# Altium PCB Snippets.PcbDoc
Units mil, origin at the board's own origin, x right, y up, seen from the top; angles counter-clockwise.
Board outline 6000 x 4000 mil, 2 copper layers (Top Layer, Bottom Layer); 15 components, 12 nets, 30 pads, 5 vias.
Unrouted connection lines stored in the file: 7.
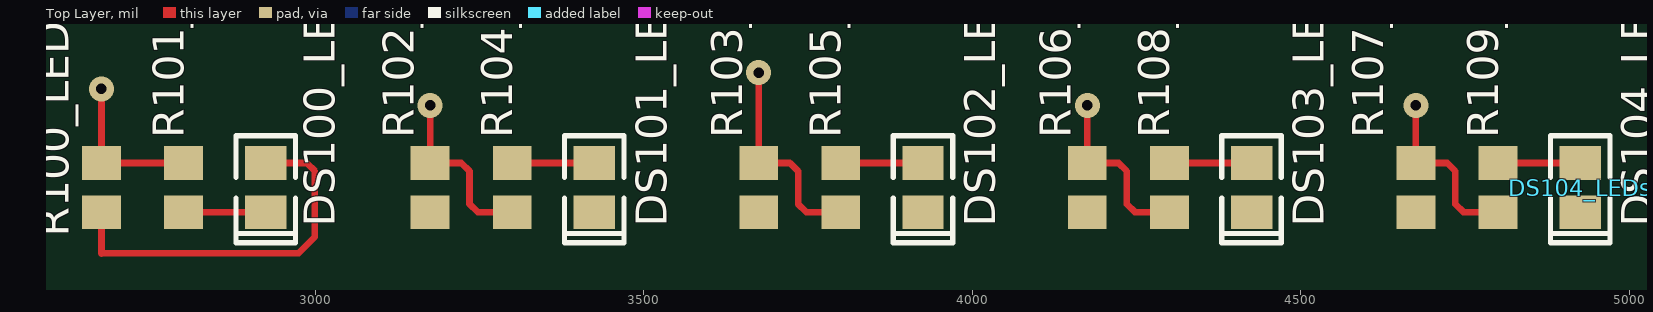
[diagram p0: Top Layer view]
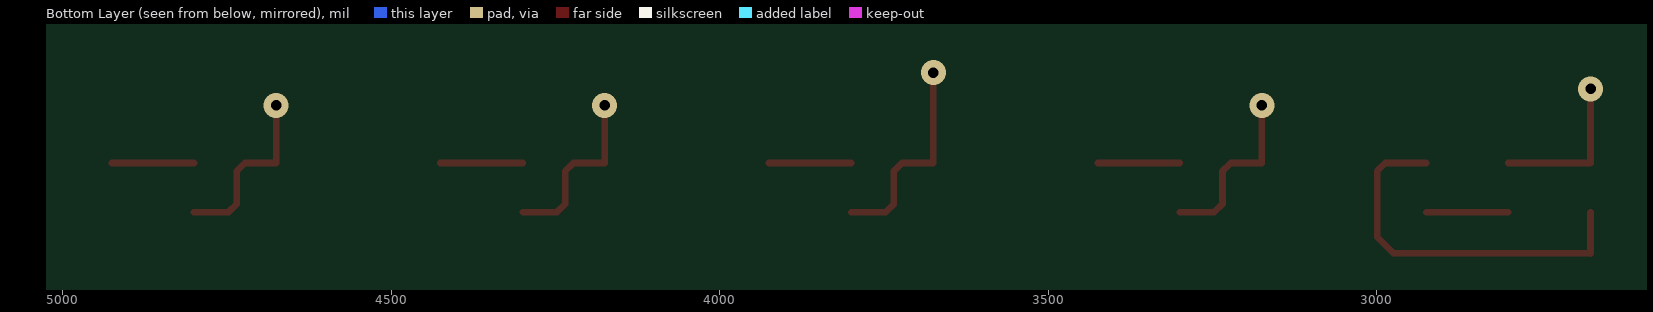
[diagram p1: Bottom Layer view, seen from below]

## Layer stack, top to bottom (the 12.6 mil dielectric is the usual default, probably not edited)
Top Solder: solder mask 0.4, Solder Resist, Dk 3.5
Top Layer: signal copper 1.4
Dielectric 1: dielectric 12.6, FR-4, Dk 4.8
Bottom Layer: signal copper 1.4
Bottom Solder: solder mask 0.4, Solder Resist, Dk 3.5

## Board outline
1000,1000 7000,1000 7000,5000 1000,5000

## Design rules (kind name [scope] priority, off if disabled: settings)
Clearance [All] p1: gap=10 ignorepadtopadclearanceinfootprint=FALSE except(0: Arc-Hole Track-Hole SMDPad-Hole THPad-Hole Via-Hole Fill-Hole Poly-Hole Region-Hole Text-Hole)
PolygonConnect [All] p1: connectstyle=Relief reliefconductorwidth=10 reliefentries=4 polygonreliefangle="90 Angle" airgapwidth=10
RoutingVias [All] p1: holewidth=28 width=50 viastyle="Through Hole" minholewidth=28 minwidth=50 maxholewidth=28 maxwidth=50
SolderMaskExpansion [All] p1: expansion=4 istentingtop=FALSE
Width [All] p1: maxlimit=10 minlimit=10 preferedwidth=10
30 further rules are at their usual default settings.

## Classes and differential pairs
net class LED[4..0]: LED0 LED1 LED2 LED3 LED4

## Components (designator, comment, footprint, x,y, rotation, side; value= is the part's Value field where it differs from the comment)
DS100_LEDs "RED" LED2013 2925,3190 r90 top
DS101_LEDs "RED" LED2013 3425,3190 r90 top
DS102_LEDs "RED" LED2013 3925,3190 r90 top
DS103_LEDs "RED" LED2013 4425,3190 r90 top
DS104_LEDs "RED" LED2013 4925,3190 r90 top
R100_LEDs "5K1 5%" RESC2012 2675,3190 r90 top
R101_LEDs "510R 5%" RESC2012 2800,3190 r90 top
R102_LEDs "5K1 5%" RESC2012 3175,3190 r90 top
R103_LEDs "5K1 5%" RESC2012 3675,3190 r90 top
R104_LEDs "510R 5%" RESC2012 3300,3190 r270 top
R105_LEDs "510R 5%" RESC2012 3800,3190 r270 top
R106_LEDs "5K1 5%" RESC2012 4175,3190 r90 top
R107_LEDs "5K1 5%" RESC2012 4675,3190 r90 top
R108_LEDs "510R 5%" RESC2012 4300,3190 r270 top
R109_LEDs "510R 5%" RESC2012 4800,3190 r270 top

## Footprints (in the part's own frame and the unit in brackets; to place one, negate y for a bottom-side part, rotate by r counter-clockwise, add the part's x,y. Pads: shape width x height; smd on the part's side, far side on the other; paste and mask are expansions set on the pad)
LED2013 [mm]
  rect 1.3x1.6 smd: 1(0.95,0) 2(-0.95,0)
  silkscreen extent -2.13,-1.15 2,1.15
RESC2012 [mm]
  rect 1.3x1.5 smd: 1(-0.95,0) 2(0.95,0)

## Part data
DS100_LEDs DS101_LEDs DS102_LEDs DS103_LEDs DS104_LEDs: library part DIO-LED-1S, "Typical GREEN SMD LED Agilent make"
R100_LEDs R101_LEDs R102_LEDs R103_LEDs R104_LEDs R105_LEDs R106_LEDs R107_LEDs R108_LEDs R109_LEDs: library part RES, "Resistor"

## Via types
v1: diameter 38, hole 16, Top Layer to Bottom Layer, 5 vias

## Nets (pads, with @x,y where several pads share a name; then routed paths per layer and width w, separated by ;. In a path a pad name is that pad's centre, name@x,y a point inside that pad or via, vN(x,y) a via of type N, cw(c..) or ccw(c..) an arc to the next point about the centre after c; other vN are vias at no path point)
3V3: DS100_LEDs.1 R100_LEDs.1 | length 577.3
  Top Layer w10: 2675,3089.66 2975,3090 2999.8,3115.2 2999.8,3215 2987.4,3227.4 DS100_LEDs.1 ; 2675,3090.39 R100_LEDs.1
GND: DS101_LEDs.2 DS102_LEDs.2 DS103_LEDs.2 DS104_LEDs.2 R102_LEDs.1 R103_LEDs.1 R106_LEDs.1 R107_LEDs.1
LED0: R100_LEDs.2 R101_LEDs.2 | length 237.6
  Top Layer w10: v1(2675,3340) R100_LEDs.2 R101_LEDs.2
LED1: R102_LEDs.2 R104_LEDs.2 | length 272.9
  Top Layer w10: v1(3175,3315) R102_LEDs.2 3222.6,3227.4 3235,3215 3235,3165 3247.4,3152.6 R104_LEDs.2
LED2: R103_LEDs.2 R105_LEDs.2 | length 322.9
  Top Layer w10: v1(3675,3365) R103_LEDs.2 3722.6,3227.4 3735,3215 3735,3165 3747.4,3152.6 R105_LEDs.2
LED3: R106_LEDs.2 R108_LEDs.2 | length 272.9
  Top Layer w10: v1(4175,3315) R106_LEDs.2 4222.6,3227.4 4235,3215 4235,3165 4247.4,3152.6 R108_LEDs.2
LED4: R107_LEDs.2 R109_LEDs.2 | length 272.9
  Top Layer w10: v1(4675,3315) R107_LEDs.2 4722.6,3227.4 4735,3215 4735,3165 4747.4,3152.6 R109_LEDs.2
NetDS100_LEDs_2: DS100_LEDs.2 R101_LEDs.1 | length 125
  Top Layer w10: R101_LEDs.1 DS100_LEDs.2
NetDS101_LEDs_1: DS101_LEDs.1 R104_LEDs.1 | length 125
  Top Layer w10: R104_LEDs.1 DS101_LEDs.1
NetDS102_LEDs_1: DS102_LEDs.1 R105_LEDs.1 | length 125
  Top Layer w10: R105_LEDs.1 DS102_LEDs.1
NetDS103_LEDs_1: DS103_LEDs.1 R108_LEDs.1 | length 125
  Top Layer w10: R108_LEDs.1 DS103_LEDs.1
NetDS104_LEDs_1: DS104_LEDs.1 R109_LEDs.1 | length 125
  Top Layer w10: R109_LEDs.1 DS104_LEDs.1

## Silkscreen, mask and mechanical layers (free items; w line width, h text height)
Top Overlay:
  text "Altium Advanced Training: '.Pcb_File_Name_No_Path'" at 1020,864.99 h60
